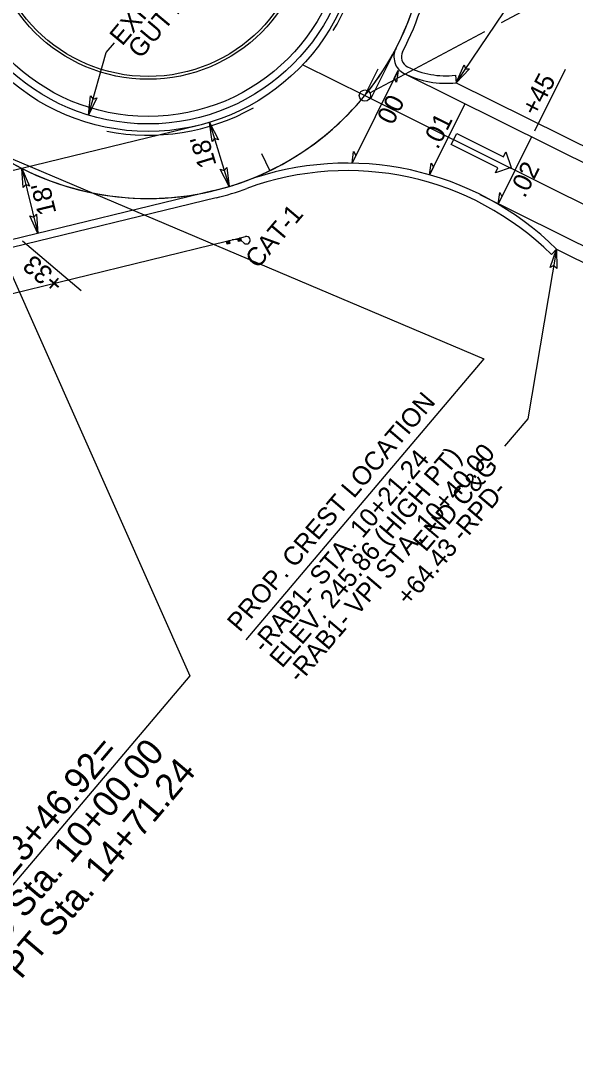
# Model space of a CAD drawing. Extents: x 1761082 to 1764358, y 421907 to 425434.
# Drawn here: x 1762189 to 1762337.6, y 422677.7 to 422958.8 of the extents above; entities that cross this region are included whole.
import ezdxf

# ---------------------------------------------------------------- set-up
doc = ezdxf.new("R2010")
doc.units = 0
for name, color, linetype in [('MARK HOOKS CENTER STRAIGHT LEFT TURN ARROW CELL', 7, 'Continuous'), ('MARK LEFT TURN ARROW CELL', 7, 'Continuous'), ('MARK UTURN ARROW CELL', 7, 'Continuous'), ('Prop Horizontal Alignment Tick Large', 7, 'Continuous'), ('Prop Mkg 3ft Min Skp 3ft Wide White', 7, 'Continuous'), ('Prop Mkg 3ft Min Skp 9ft White', 7, 'Continuous'), ('Prop Mkg 3ft Min Skp 9ft Wide White', 7, 'Continuous'), ('Prop Mkg Min Skp 6ft Yellow', 7, 'Continuous'), ('Prop Mkg Skp Wht', 7, 'Continuous'), ('Prop Mkg Solid White Diagonals', 7, 'Continuous'), ('Prop Mkg Solid White Gore Line', 7, 'Continuous'), ('Prop Mkg Solid White Multiple Diagonals V8i', 7, 'Continuous'), ('Prop Mkg Solid White Stop Bar', 7, 'Continuous'), ('Prop Mkg Solid Yel Skip LT', 7, 'Continuous'), ('Prop Mkg Solid Yel Skip RT', 7, 'Continuous'), ('Prop Mkg Solid Yellow Diagonals', 7, 'Continuous'), ('Prop Mkg Solid Yellow Edge Line', 7, 'Continuous'), ('Prop Mkg Solid Yellow Lane Line', 7, 'Continuous'), ('Prop Mkg Yld Lin', 7, 'Continuous'), ('Prop Mkr Yel 80ft Spc', 7, 'Continuous'), ('Scratch_Level_0', 7, 'Continuous'), ('Scratch_Level_1', 7, 'Continuous'), ('Scratch_Level_5', 7, 'Continuous')]:
    doc.layers.add(name, color=color, linetype=linetype)

msp = doc.modelspace()

# ---------------------------------------------------------------- linework, layer by layer
at = {"layer": 'MARK HOOKS CENTER STRAIGHT LEFT TURN ARROW CELL'}
msp.add_line((1762255.76, 422918.6), (1762253.58, 422923.11), dxfattribs=at)
at = {"layer": 'MARK LEFT TURN ARROW CELL'}
for p, q in [((1762305.52, 422944.19), (1762305.74, 422942.21)), ((1762241.31, 422911.3), (1762183.21, 422897.16)), ((1762331.29, 422896.09), (1762332.7, 422897.52))]:
    msp.add_line(p, q, dxfattribs=at)
for centre, radius, start, end in [((1762223.1, 422986.12), 77, 332.4717, 12.6858), ((1762294.04, 422949.14), 3, 152.4717, 243.5483), ((1762302.95, 422967.05), 23, 243.5483, 276.4082), ((1762276.48, 422840.6), 78, 45.3535, 110.146), ((1762223.1, 422986.12), 77, 283.6821, 290.146)]:
    msp.add_arc(centre, radius, start, end, dxfattribs=at)
at = {"layer": 'MARK UTURN ARROW CELL'}
for points in [[(1762317.87, 422958.33), (1762398.98, 423001.7), (1762481.78, 423099.43)], [(1762282.57, 422939.46), (1762313.45, 422955.97)], [(1762165.77, 422937.12), (1762234.28, 422783.03), (1762150.66, 422684.32)]]:
    msp.add_lwpolyline(points, dxfattribs=at)
msp.add_circle((1762281.25, 422938.75), 1.5, dxfattribs=at)
msp.add_circle((1762281.25, 422938.75), 1.5, dxfattribs=at)
at = {"layer": 'Prop Horizontal Alignment Tick Large'}
msp.add_line((1762281.25, 422938.75), (1762284.81, 422945.92), dxfattribs=at)
at = {"layer": 'Prop Mkg 3ft Min Skp 3ft Wide White'}
msp.add_line((1762281.25, 422938.75), (1762449.48, 422855.05), dxfattribs=at)
for start, end in [(320.8368, 60.0363), (219.4239, 320.8368)]:
    msp.add_arc((1762223.1, 422986.12), 75, start, end, dxfattribs=at)
at = {"layer": 'Prop Mkg 3ft Min Skp 9ft White'}
msp.add_circle((1762223.1, 422986.12), 55, dxfattribs=at)
at = {"layer": 'Prop Mkg 3ft Min Skp 9ft Wide White'}
msp.add_line((1762165.78, 422880.57), (1762244.15, 422899.64), dxfattribs=at)
at = {"layer": 'Prop Mkg Skp Wht'}
for p, q in [((1762291.81, 422944.67), (1762453.93, 422864.01)), ((1762240.84, 422913.25), (1762182.73, 422899.1)), ((1762312.12, 422912.23), (1762445.02, 422846.1))]:
    msp.add_line(p, q, dxfattribs=at)
for centre, radius, start, end in [((1762223.1, 422986.12), 75, 332.4717, 12.6858), ((1762294.04, 422949.14), 5, 152.4717, 243.5483), ((1762276.48, 422840.6), 80, 45.3535, 110.146), ((1762223.1, 422986.12), 75, 283.6821, 290.146)]:
    msp.add_arc(centre, radius, start, end, dxfattribs=at)
at = {"layer": 'Prop Mkg Solid White Diagonals'}
for radius in [53, 43]:
    msp.add_circle((1762223.1, 422986.12), radius, dxfattribs=at)
at = {"layer": 'Prop Mkg Solid White Gore Line'}
for radius in [43, 42.25]:
    msp.add_circle((1762223.1, 422986.12), radius, dxfattribs=at)
at = {"layer": 'Prop Mkg Solid White Multiple Diagonals V8i'}
for p, q in [((1762264.59, 422947.04), (1762281.25, 422938.75)), ((1762236.58, 422930.74), (1762189.22, 422919.21))]:
    msp.add_line(p, q, dxfattribs=at)
for radius in [57, 53]:
    msp.add_circle((1762223.1, 422986.12), radius, dxfattribs=at)
for radius, start, end in [(58, 328.9268, 31.3511), (75, 290.146, 330.9741), (58, 259.0098, 299.1293)]:
    msp.add_arc((1762223.1, 422986.12), radius, start, end, dxfattribs=at)
at = {"layer": 'Prop Mkg Solid White Stop Bar'}
for p, q in [((1762305.74, 422942.21), (1762455.72, 422867.59)), ((1762332.7, 422897.52), (1762443.24, 422842.52))]:
    msp.add_line(p, q, dxfattribs=at)
msp.add_arc((1762302.95, 422967.05), 25, 243.5483, 276.4082, dxfattribs=at)
at = {"layer": 'Prop Mkg Solid Yel Skip RT'}
for p, q in [((1762334.99, 422945.74), (1762326.75, 422929.19)), ((1762239.6, 422931.56), (1762244.81, 422914.33)), ((1762189.22, 422919.21), (1762193.48, 422901.72)), ((1762189.36, 422899.75), (1762205.13, 422886.39))]:
    msp.add_line(p, q, dxfattribs=at)
for points in [[(1762305.74, 422942.21), (1762331.35, 422980.07), (1762333.57, 422982.69)], [(1762207.08, 422933.5), (1762211.86, 422950.27), (1762214.07, 422952.89)], [(1762332.7, 422897.52), (1762324.97, 422851.99), (1762318.73, 422844.64)]]:
    msp.add_lwpolyline(points, dxfattribs=at)
at = {"layer": 'Prop Mkg Solid Yellow Diagonals'}
for p, q in [((1762304.41, 422925.61), (1762305.89, 422928.56)), ((1762305.89, 422928.56), (1762318.41, 422922.3)), ((1762316.93, 422919.35), (1762304.41, 422925.61)), ((1762318.41, 422922.3), (1762319.08, 422923.64)), ((1762319.08, 422923.64), (1762320.51, 422919.46)), ((1762320.51, 422919.46), (1762316.26, 422918)), ((1762316.26, 422918), (1762316.93, 422919.35))]:
    msp.add_line(p, q, dxfattribs=at)
at = {"layer": 'Prop Mkg Solid Yellow Edge Line'}
msp.add_arc((1762223.1, 422986.12), 75, 243.1463, 283.6821, dxfattribs=at)
at = {"layer": 'Prop Mkg Solid Yellow Lane Line'}
for points in [[(1762309.33, 422945.94), (1762305.74, 422942.21), (1762307.86, 422946.96), (1762308.25, 422945.92)], [(1762209.32, 422938.17), (1762207.08, 422933.5), (1762207.61, 422938.69), (1762208.31, 422937.81)], [(1762240.24, 422926.42), (1762239.6, 422931.56), (1762241.96, 422926.91), (1762240.9, 422927.27)], [(1762189.57, 422914.04), (1762189.22, 422919.21), (1762191.31, 422914.43), (1762190.28, 422914.85)], [(1762244.18, 422919.47), (1762244.81, 422914.33), (1762242.46, 422918.98), (1762243.52, 422918.62)], [(1762193.12, 422906.88), (1762193.48, 422901.72), (1762191.38, 422906.49), (1762192.42, 422906.07)], [(1762330.98, 422892.63), (1762332.7, 422897.52), (1762332.74, 422892.31), (1762331.95, 422893.1)]]:
    msp.add_lwpolyline(points, close=True, dxfattribs=at)
at = {"layer": 'Prop Mkg Yld Lin'}
for p, q in [((1762244.15, 422899.64), (1762247.59, 422900.48)), ((1762244.15, 422899.64), (1762244.83, 422899.81)), ((1762244.34, 422898.86), (1762244.15, 422899.64)), ((1762244.15, 422899.64), (1762245.02, 422899.03)), ((1762244.83, 422899.81), (1762244.34, 422898.86)), ((1762245.02, 422899.03), (1762244.34, 422898.86)), ((1762244.83, 422899.81), (1762245.02, 422899.03)), ((1762247.61, 422900.07), (1762245.66, 422900.01)), ((1762247.17, 422900.38), (1762247.85, 422900.54)), ((1762247.36, 422899.6), (1762247.17, 422900.38)), ((1762247.17, 422900.38), (1762248.04, 422899.76)), ((1762247.85, 422900.54), (1762247.36, 422899.6)), ((1762248.04, 422899.76), (1762247.36, 422899.6)), ((1762247.59, 422900.48), (1762249.26, 422900.89)), ((1762247.72, 422900.51), (1762247.59, 422900.48)), ((1762247.85, 422900.54), (1762248.04, 422899.76)), ((1762248.87, 422899.16), (1762248.02, 422899.86))]:
    msp.add_line(p, q, dxfattribs=at)
msp.add_ellipse((1762249.5, 422899.92), major_axis=(-0.235, 0.965), ratio=0.995379, start_param=2.210226, end_param=6.283185, dxfattribs=at)
at = {"layer": 'Prop Mkr Yel 80ft Spc'}
for start, end in [(320.8368, 60.0363), (219.4239, 320.8368)]:
    msp.add_arc((1762223.1, 422986.12), 75, start, end, dxfattribs=at)
at = {"layer": 'Scratch_Level_0'}
for p, q in [((1762289.56, 422951.37), (1762282.88, 422937.94)), ((1762189.22, 422919.21), (1762179.85, 422916.93))]:
    msp.add_line(p, q, dxfattribs=at)
msp.add_arc((1762223.1, 422986.12), 75, 211.4287, 243.1463, dxfattribs=at)
at = {"layer": 'Scratch_Level_1'}
msp.add_lwpolyline([(1762180.78, 422924.2), (1762313.18, 422868.04), (1762249.34, 422792.68)], dxfattribs=at)
at = {"layer": 'Scratch_Level_5'}
for p, q in [((1762290.18, 422945.48), (1762277.8, 422920.59)), ((1762308.09, 422936.57), (1762298.59, 422917.49)), ((1762325.99, 422927.66), (1762317, 422909.58))]:
    msp.add_line(p, q, dxfattribs=at)
for points in [[(1762290.18, 422945.48), (1762289.74, 422942.35), (1762289.15, 422943.41)], [(1762277.8, 422920.59), (1762278.24, 422923.72), (1762278.83, 422922.66)], [(1762298.59, 422917.49), (1762299.03, 422920.62), (1762299.62, 422919.56)], [(1762317, 422909.58), (1762317.44, 422912.71), (1762318.03, 422911.65)]]:
    msp.add_lwpolyline(points, close=True, dxfattribs=at)

# ---------------------------------------------------------------- texts
at = {"layer": 'MARK UTURN ARROW CELL'}
for s, p in [('-L- POT Sta.  23+46.92=', (1762149.13, 422684.58)), ('-RAB1- PC Sta. 10+00.00', (1762158.35, 422680.29)), ('-RAB1- PT Sta. 14+71.24', (1762167.46, 422675.9))]:
    msp.add_text(s, height=7, rotation=49.7301, dxfattribs=at).set_placement(p)
at = {"layer": 'Prop Mkg Min Skp 6ft Yellow'}
for s, p in [('00', (1762288.75, 422930.61)), ('.01', (1762300.78, 422924.06)), ('.02', (1762324.15, 422911.02))]:
    msp.add_text(s, height=5, rotation=63.5483, dxfattribs=at).set_placement(p)
at = {"layer": 'Prop Mkg Solid Yel Skip LT'}
for s, rotation, p in [('EXPRESSWAY', 50.1302, (1762216.16, 422951.85)), ('GUTTER', 50.1302, (1762221.07, 422948.39)), ('+45', 63.0251, (1762327.42, 422932.92)), ("18'", 106.8316, (1762241.5, 422920.17)), ("18'", 103.6821, (1762198.51, 422907.31)), ('+33', 139.7301, (1762200.91, 422888.94)), ('END C&G', 49.7301, (1762297.55, 422816.02)), ('+64.43 -RPD-', 49.7301, (1762293.08, 422801.47))]:
    msp.add_text(s, height=5, rotation=rotation, dxfattribs=at).set_placement(p)
at = {"layer": 'Prop Mkg Yld Lin'}
msp.add_text('CAT-1', height=5, rotation=49.7301, dxfattribs=at).set_placement((1762252.52, 422892.07))
at = {"layer": 'Scratch_Level_1'}
for s, p in [('PROP. CREST LOCATION', (1762247.68, 422794.48)), ('-RAB1- STA. 10+21.24', (1762254.34, 422788.83)), ('ELEV. 245.86 (HIGH PT)', (1762259.03, 422784.86)), ('-RAB1- VPI STA. 10+40.00', (1762263.81, 422780.81))]:
    msp.add_text(s, height=5, rotation=49.5644, dxfattribs=at).set_placement(p)

doc.saveas('drawing.dxf')
